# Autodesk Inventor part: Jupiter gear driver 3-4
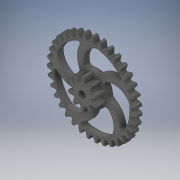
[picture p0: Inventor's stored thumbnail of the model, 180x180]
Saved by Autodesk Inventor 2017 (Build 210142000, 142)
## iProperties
Created: 2016-07
Part Number: Jupiter gear driver 3-4
Material: Generic
Document SubType Name: Modeling
Designer: Stan
Density: 1 g/cm^3
Appearance: Gray
Author: Stan
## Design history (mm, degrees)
sketch "Sketch1"
  geometry: A1 r 21.061 centre (26.745, -30.13) between (8.221, -40.15) and (11.162, -44.298); A2 r 21.061 centre (26.745, -30.13) between (8.221, -40.15) and (11.162, -44.298); A3 r 21.061 centre (-14.453, -37.606) between (5.115, -45.395) and (6.411, -40.479); A4 r 21.061 centre (-14.453, -37.606) between (5.115, -45.395) and (6.411, -40.479); A5 r 21.061 centre (31.695, -24.87) between (15.258, -38.037) and (18.892, -41.593); A6 r 21.061 centre (31.695, -24.87) between (15.258, -38.037) and (18.892, -41.593); A7 r 21.061 centre (-7.505, -39.582) between (13.138, -43.752) and (13.536, -38.683); A8 r 21.061 centre (-7.505, -39.582) between (13.138, -43.752) and (13.536, -38.683); A9 r 21.061 centre (35.626, -18.811) between (21.804, -34.701) and (26.015, -37.551); A10 r 21.061 centre (35.626, -18.811) between (21.804, -34.701) and (26.015, -37.551); A11 r 21.061 centre (-0.317, -40.286) between (20.739, -40.703) and (20.226, -35.645); A12 r 21.061 centre (-0.317, -40.286) between (20.739, -40.703) and (20.226, -35.645); A13 r 21.061 centre (38.413, -12.148) between (27.65, -30.25) and (32.302, -32.302); A14 r 21.061 centre (38.413, -12.148) between (27.65, -30.25) and (32.302, -32.302); A15 r 21.061 centre (6.881, -39.696) between (27.674, -36.346) and (26.265, -31.461); A16 r 21.061 centre (6.881, -39.696) between (27.674, -36.346) and (26.265, -31.461); A17 r 21.061 centre (39.964, -5.094) between (32.607, -24.827) and (37.551, -26.015); A18 r 21.061 centre (39.964, -5.094) between (32.607, -24.827) and (37.551, -26.015); A19 r 21.061 centre (13.859, -37.829) between (33.719, -30.82) and (31.461, -26.265); A20 r 21.061 centre (13.859, -37.829) between (33.719, -30.82) and (31.461, -26.265); A21 r 21.061 centre (40.232, 2.124) between (36.516, -18.606) and (41.593, -18.892); A22 r 21.061 centre (40.232, 2.124) between (36.516, -18.606) and (41.593, -18.892); A23 r 21.061 centre (20.391, -34.746) between (38.68, -24.304) and (35.645, -20.226); A24 r 21.061 centre (20.391, -34.746) between (38.68, -24.304) and (35.645, -20.226); A25 r 21.061 centre (39.206, 9.274) between (39.252, -11.787) and (44.298, -11.162); A26 r 21.061 centre (39.206, 9.274) between (39.252, -11.787) and (44.298, -11.162); A27 r 21.061 centre (26.267, -30.547) between (42.398, -17.007) and (38.683, -13.536); A28 r 21.061 centre (26.267, -30.547) between (42.398, -17.007) and (38.683, -13.536); A29 r 21.061 centre (36.92, 16.125) between (40.725, -4.589) and (45.579, -3.073); A30 r 21.061 centre (36.92, 16.125) between (40.725, -4.589) and (45.579, -3.073); A31 r 21.061 centre (31.299, -25.366) between (44.754, -9.163) and (40.479, -6.411); A32 r 21.061 centre (31.299, -25.366) between (44.754, -9.163) and (40.479, -6.411); A33 r 21.061 centre (33.447, 22.458) between (40.89, 2.757) and (45.395, 5.115); A34 r 21.061 centre (33.447, 22.458) between (40.89, 2.757) and (45.395, 5.115); A35 r 21.061 centre (35.326, -19.37) between (45.671, -1.025) and (40.973, 0.92); A36 r 21.061 centre (35.326, -19.37) between (45.671, -1.025) and (40.973, 0.92); A37 r 21.061 centre (28.9, 28.07) between (39.741, 10.014) and (43.752, 13.138); A38 r 21.061 centre (28.9, 28.07) between (39.741, 10.014) and (43.752, 13.138); A39 r 21.061 centre (38.217, -12.751) between (45.12, 7.146) and (40.15, 8.221); A40 r 21.061 centre (38.217, -12.751) between (45.12, 7.146) and (40.15, 8.221); A41 r 21.061 centre (23.423, 32.779) between (37.314, 16.949) and (40.703, 20.739); A42 r 21.061 centre (23.423, 32.779) between (37.314, 16.949) and (40.703, 20.739); A43 r 21.061 centre (39.879, -5.722) between (43.119, 15.088) and (38.037, 15.258); A44 r 21.061 centre (39.879, -5.722) between (43.119, 15.088) and (38.037, 15.258); A45 r 21.061 centre (17.194, 36.434) between (33.688, 23.339) and (36.346, 27.674); A46 r 21.061 centre (17.194, 36.434) between (33.688, 23.339) and (36.346, 27.674); A47 r 21.061 centre (40.26, 1.491) between (39.732, 22.545) and (34.701, 21.804); A48 r 21.061 centre (40.26, 1.491) between (39.732, 22.545) and (34.701, 21.804); A49 r 21.061 centre (10.412, 38.919) between (28.979, 28.979) and (30.82, 33.719); A50 r 21.061 centre (10.412, 38.919) between (28.979, 28.979) and (30.82, 33.719); A51 r 21.061 centre (39.347, 8.655) between (35.068, 29.277) and (30.25, 27.65); A52 r 21.061 centre (39.347, 8.655) between (35.068, 29.277) and (30.25, 27.65); A53 r 21.061 centre (3.295, 40.153) between (23.339, 33.688) and (24.304, 38.68); A54 r 21.061 centre (3.295, 40.153) between (23.339, 33.688) and (24.304, 38.68); A55 r 21.061 centre (37.169, 15.542) between (29.277, 35.068) and (24.827, 32.607); A56 r 21.061 centre (37.169, 15.542) between (29.277, 35.068) and (24.827, 32.607); A57 r 21.061 centre (-3.927, 40.096) between (16.949, 37.314) and (17.007, 42.398); A58 r 21.061 centre (-3.927, 40.096) between (16.949, 37.314) and (17.007, 42.398); A59 r 21.061 centre (33.797, 21.929) between (22.545, 39.732) and (18.606, 36.516); A60 r 21.061 centre (33.797, 21.929) between (22.545, 39.732) and (18.606, 36.516); A61 r 21.061 centre (-11.023, 38.75) between (10.014, 39.741) and (9.163, 44.754); A62 r 21.061 centre (-11.023, 38.75) between (10.014, 39.741) and (9.163, 44.754); A63 r 21.061 centre (29.338, 27.611) between (15.088, 43.119) and (11.787, 39.252); A64 r 21.061 centre (29.338, 27.611) between (15.088, 43.119) and (11.787, 39.252)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; 1 further point
  constraints: 592 point on circle, 296 centre point, 8 horizontal alignment, 862 other
extrude "Extrusion1" new body sketch "Sketch1" distance "d0" = 6.35; taper "d1" = 0 deg
sketch "Sketch3"
  geometry: A1 r 11.357 centre (-12.259, -5.358) between (-9.02, 5.527) and (-14.115, 5.847); A2 r 11.357 centre (-12.259, -5.358) between (-9.02, 5.527) and (-14.115, 5.847); A3 r 11.357 centre (1.307, 13.315) between (-9.922, 11.617) and (-8.044, 6.87); A4 r 11.357 centre (1.307, 13.315) between (-9.922, 11.617) and (-8.044, 6.87); A5 r 11.357 centre (-6.769, -11.54) between (-10.546, -0.83) and (-14.856, -3.567); A6 r 11.357 centre (-6.769, -11.54) between (-10.546, -0.83) and (-14.856, -3.567); A7 r 11.357 centre (-6.769, 11.54) between (-14.856, 3.567) and (-10.546, 0.83); A8 r 11.357 centre (-6.769, 11.54) between (-14.856, 3.567) and (-10.546, 0.83); A9 r 11.357 centre (1.307, -13.315) between (-8.044, -6.87) and (-9.922, -11.617); A10 r 11.357 centre (1.307, -13.315) between (-8.044, -6.87) and (-9.922, -11.617); A11 r 11.357 centre (-12.259, 5.358) between (-14.115, -5.847) and (-9.02, -5.527); A12 r 11.357 centre (-12.259, 5.358) between (-14.115, -5.847) and (-9.02, -5.527); A13 r 11.357 centre (8.884, -10.004) between (-2.47, -10.287) and (-1.199, -15.231); A14 r 11.357 centre (8.884, -10.004) between (-2.47, -10.287) and (-1.199, -15.231); A15 r 11.357 centre (-13.067, -2.871) between (-7.983, -13.027) and (-4.048, -9.774); A16 r 11.357 centre (-13.067, -2.871) between (-7.983, -13.027) and (-4.048, -9.774); A17 r 11.357 centre (13.067, -2.871) between (4.048, -9.774) and (7.983, -13.027); A18 r 11.357 centre (13.067, -2.871) between (4.048, -9.774) and (7.983, -13.027); A19 r 11.357 centre (-8.884, -10.004) between (1.199, -15.231) and (2.47, -10.287); A20 r 11.357 centre (-8.884, -10.004) between (1.199, -15.231) and (2.47, -10.287); A21 r 11.357 centre (12.259, 5.358) between (9.02, -5.527) and (14.115, -5.847); A22 r 11.357 centre (12.259, 5.358) between (9.02, -5.527) and (14.115, -5.847); A23 r 11.357 centre (-1.307, -13.315) between (9.922, -11.617) and (8.044, -6.87); A24 r 11.357 centre (-1.307, -13.315) between (9.922, -11.617) and (8.044, -6.87); A25 r 11.357 centre (6.769, 11.54) between (10.546, 0.83) and (14.856, 3.567); A26 r 11.357 centre (6.769, 11.54) between (10.546, 0.83) and (14.856, 3.567); A27 r 11.357 centre (6.769, -11.54) between (14.856, -3.567) and (10.546, -0.83); A28 r 11.357 centre (6.769, -11.54) between (14.856, -3.567) and (10.546, -0.83); A29 r 11.357 centre (-1.307, 13.315) between (8.044, 6.87) and (9.922, 11.617); A30 r 11.357 centre (-1.307, 13.315) between (8.044, 6.87) and (9.922, 11.617); A31 r 11.357 centre (12.259, -5.358) between (14.115, 5.847) and (9.02, 5.527); A32 r 11.357 centre (12.259, -5.358) between (14.115, 5.847) and (9.02, 5.527); A33 r 11.357 centre (-8.884, 10.004) between (2.47, 10.287) and (1.199, 15.231); A34 r 11.357 centre (-8.884, 10.004) between (2.47, 10.287) and (1.199, 15.231); A35 r 11.357 centre (13.067, 2.871) between (7.983, 13.027) and (4.048, 9.774); A36 r 11.357 centre (13.067, 2.871) between (7.983, 13.027) and (4.048, 9.774); A37 r 11.357 centre (1.307, 13.315) between (-9.922, 11.617) and (-8.044, 6.87); A38 r 11.357 centre (-12.259, -5.358) between (-9.02, 5.527) and (-14.115, 5.847); A39 r 11.357 centre (-6.769, 11.54) between (-14.856, 3.567) and (-10.546, 0.83); A40 r 11.357 centre (-6.769, -11.54) between (-10.546, -0.83) and (-14.856, -3.567); A41 r 11.357 centre (-12.259, 5.358) between (-14.115, -5.847) and (-9.02, -5.527); A42 r 11.357 centre (1.307, -13.315) between (-8.044, -6.87) and (-9.922, -11.617); A43 r 11.357 centre (-13.067, -2.871) between (-7.983, -13.027) and (-4.048, -9.774); A44 r 11.357 centre (8.884, -10.004) between (-2.47, -10.287) and (-1.199, -15.231); A45 r 11.357 centre (-8.884, -10.004) between (1.199, -15.231) and (2.47, -10.287); A46 r 11.357 centre (13.067, -2.871) between (4.048, -9.774) and (7.983, -13.027); A47 r 11.357 centre (-1.307, -13.315) between (9.922, -11.617) and (8.044, -6.87); A48 r 11.357 centre (12.259, 5.358) between (9.02, -5.527) and (14.115, -5.847); A49 r 11.357 centre (6.769, -11.54) between (14.856, -3.567) and (10.546, -0.83); A50 r 11.357 centre (6.769, 11.54) between (10.546, 0.83) and (14.856, 3.567); A51 r 11.357 centre (12.259, -5.358) between (14.115, 5.847) and (9.02, 5.527); A52 r 11.357 centre (-1.307, 13.315) between (8.044, 6.87) and (9.922, 11.617); A53 r 11.357 centre (13.067, 2.871) between (7.983, 13.027) and (4.048, 9.774); A54 r 11.357 centre (-8.884, 10.004) between (2.47, 10.287) and (1.199, 15.231); A55 r 11.357 centre (8.884, 10.004) between (-1.199, 15.231) and (-2.47, 10.287); A56 r 11.357 centre (-13.067, 2.871) between (-4.048, 9.774) and (-7.983, 13.027); A57 r 11.357 centre (-13.067, 2.871) between (-4.048, 9.774) and (-7.983, 13.027); A58 r 11.357 centre (-13.067, 2.871) between (-4.048, 9.774) and (-7.983, 13.027); A59 r 11.357 centre (8.884, 10.004) between (-1.199, 15.231) and (-2.47, 10.287); A60 r 11.357 centre (8.884, 10.004) between (-1.199, 15.231) and (-2.47, 10.287); A61 r 11.357 centre (1.307, 13.315) between (-9.922, 11.617) and (-8.044, 6.87); A62 r 11.357 centre (-13.067, 2.871) between (-4.048, 9.774) and (-7.983, 13.027); A63 r 11.357 centre (8.884, 10.004) between (-1.199, 15.231) and (-2.47, 10.287); A64 r 11.357 centre (-8.884, 10.004) between (2.47, 10.287) and (1.199, 15.231)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; 1 further point
  constraints: 160 point on circle, 80 centre point, 8 horizontal alignment, 8 vertical alignment, 224 other
extrude "Extrusion3" join sketch "Sketch3" distance "d5" = 9.525; taper "d6" = 0 deg
sketch "Sketch4"
  geometry: C1 r 3.175 at (0, 0); 1 further point
  constraints: 1 centre point, 1 coincident
  dimensions: "d9" = 6.35 diameter of C1
extrude "Extrusion4" cut sketch "Sketch4" distance "d10" = 15.875; taper "d11" = 0 deg
fillet "Fillet2" dims "d13" = 3.175
fillet "Fillet3" dims "d14" = 0.79375
fillet "Fillet4" dims "d15" = 0.79375
fillet "Fillet5" dims "d16" = 0.79375
fillet "Fillet6" dims "d17" = 0.79375
fillet "Fillet7" dims "d18" = 0.79375
fillet "Fillet8" dims "d19" = 0.79375
fillet "Fillet9" dims "d20" = 0.79375
body "Solid1"
